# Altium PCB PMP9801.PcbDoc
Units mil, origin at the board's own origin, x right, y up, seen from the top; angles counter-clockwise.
Board outline 2509.99 x 1210.36 mil, 2 copper layers (Top Layer, Bottom Layer), stack 62 mil thick; 26 components, 15 nets, 64 pads, 17 vias.
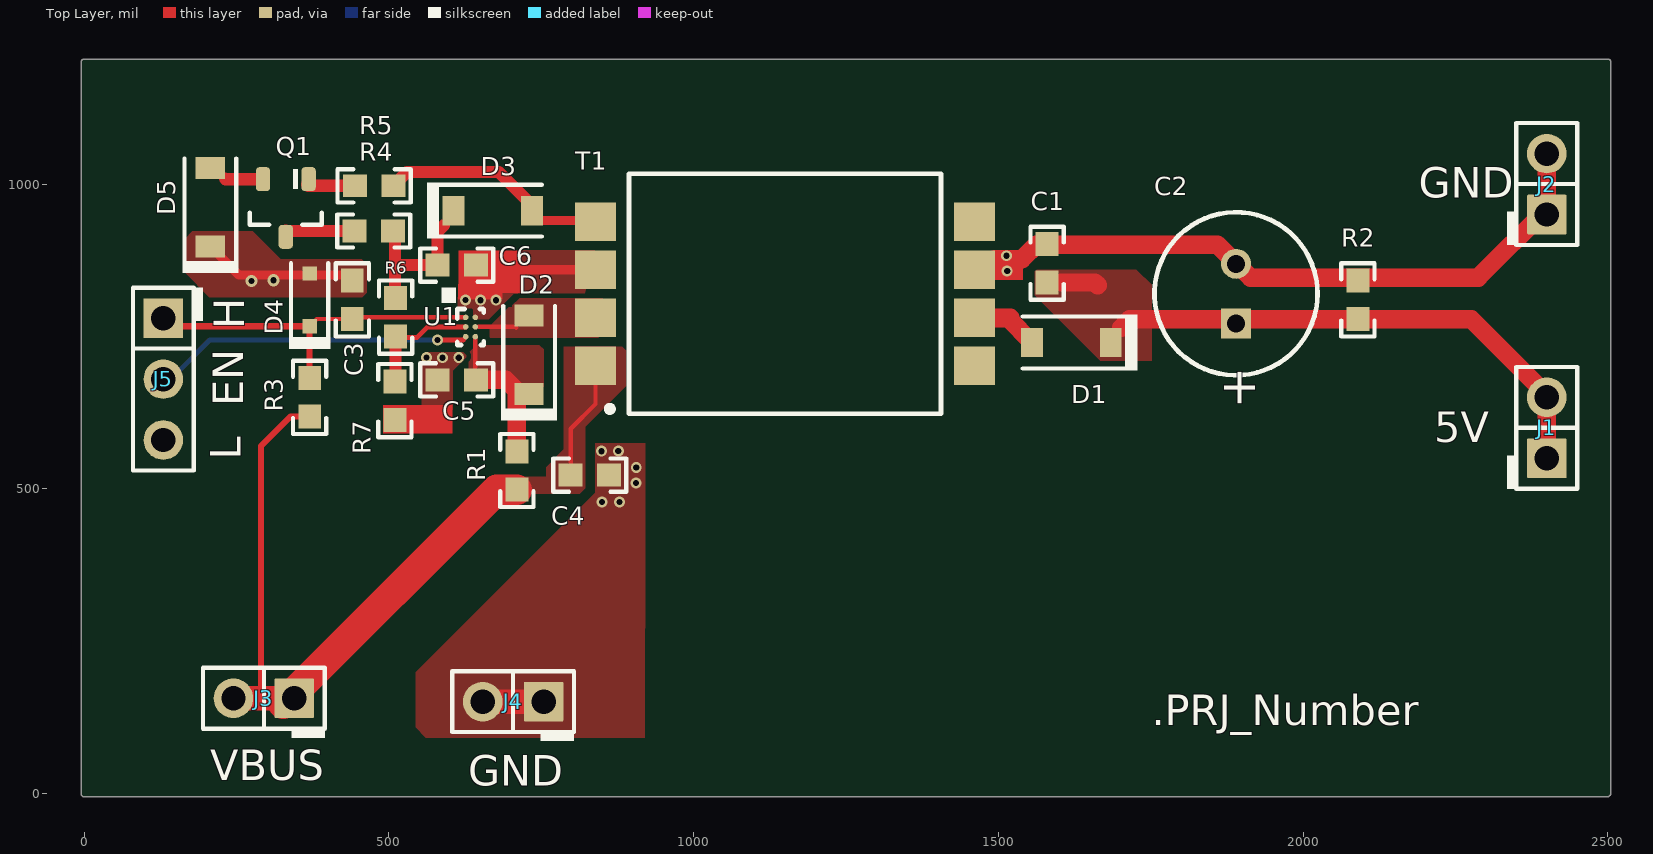
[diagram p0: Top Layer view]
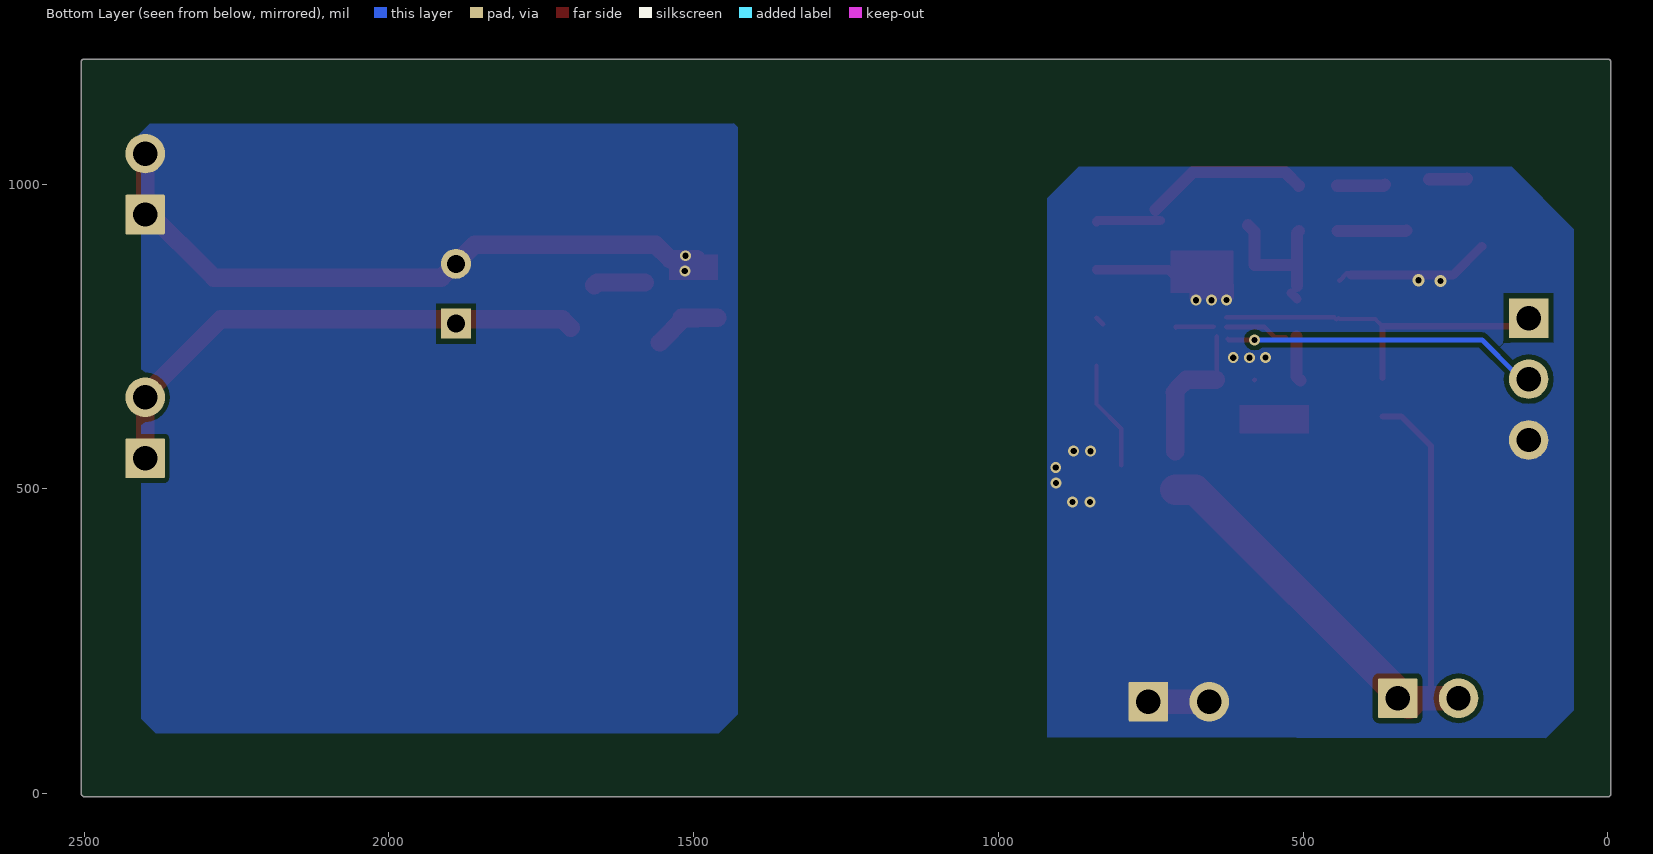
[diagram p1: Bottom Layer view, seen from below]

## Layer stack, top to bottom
Top Solder: solder mask 0.4, Solder Resist, Dk 3.5
Top Layer: signal copper 1.4
Dielectric1: core 59.2, FR-4, Dk 4.8
Bottom Layer: signal copper 1.4
Bottom Solder: solder mask 0.4, Solder Resist, Dk 3.5

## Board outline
-4.87,-0.06 cw(c0.06,0.85) -4.96,0.85 -4.96,1199.94 cw(c0.06,1199.94) 0.06,1204.96 2500.02,1204.96 cw(c2500.02,1199.94) 2505.04,1199.94 2505.04,0.48 cw(c2500.02,0.48) 2503.55,-3.08 2503.57,-3.06 2502.7,-3.93 2502.71,-3.92 cw(c2499.15,-0.39) 2499.15,-5.4 0.13,-5.4 cw(c0.13,-0.39)

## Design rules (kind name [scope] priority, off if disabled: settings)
AcuteAngle [All] p1: minimum=4.50000000000000E+0001 checktracksonly=FALSE
AssemblyTestPointUsage [All] p1: valid=2
Clearance "U1 Clearance" [InComponent('U1')] p1: gap=4
Clearance Clearance_BoardEdge [OnCopper and Not InComponentClass('Logo') and not InComponentClass('FiducialMark') and not InRegion(1000,500,4000,800) vs IsKeepOut] p2: gap=30
Clearance [All] p3: gap=8
ComponentClearance ComponentClearance_MountingHoles_FiducialMarks [InComponentClass('Mounting Holes') vs InComponentClass('FiducialMark')] p1: gap=50 collisioncheckmode=3 verticalgap=10 showdistances=FALSE
ComponentClearance ComponentClearance_SHUNT [InComponentClass('Shunt')] p2: gap=0 collisioncheckmode=3 verticalgap=0 showdistances=FALSE
ComponentClearance ComponentClearance_Logo [All] p3: gap=10 collisioncheckmode=3 verticalgap=10 showdistances=FALSE
ComponentClearance ComponentClearance_ScrewToNut [(HasFootprint('NY PMS 440 0025 PH')) vs (HasFootprint('Keystone_1902C'))] p4: gap=5 collisioncheckmode=3 verticalgap=10 showdistances=FALSE
ComponentClearance ComponentClearance_MountingHoles [InComponentClass('Mounting Holes')] p5: gap=250 collisioncheckmode=3 verticalgap=100000 showdistances=FALSE
ComponentClearance ComponentClearance_SmallPassives [HasFootprint('0201*') or HasFootprint('0402*') or HasFootprint('0508') or HasFootprint('0603*') or HasFootprint('0612') or HasFootprint('0805*') or HasFootprint('0815*') or HasFootprint('0830*') or HasFootprint('1206*') or HasFootprint('1210*') or HasFootprint('1808*') or HasFootprint('1812*') or HasFootprint('1825*') or HasFootprint('2010*') or HasFootprint('2220*') or HasFootprint('2225*') or HasFootprint('2512*') or HasFootprint('2728*') or HasFootprint('3518*') vs HasFootprint('0201*') or HasFootprint('0402*') or HasFootprint('0508') or HasFootprint('0603*') or HasFootprint('0612') or HasFootprint('0805*') or HasFootprint('0815*') or HasFootprint('0830*') or HasFootprint('1206*') or HasFootprint('1210*') or HasFootprint('1808*') or HasFootprint('1812*') or HasFootprint('1825*') or HasFootprint('2010*') or HasFootprint('2220*') or HasFootprint('2225*') or HasFootprint('2512*') or HasFootprint('2728*') or HasFootprint('3518*')] p6: gap=20 collisioncheckmode=3 verticalgap=10 showdistances=FALSE
ComponentClearance ComponentClearance_THtoSMT [IsThruComponent vs IsSMTComponent] p7 off: gap=10 collisioncheckmode=3 verticalgap=100000 showdistances=FALSE
ComponentClearance ComponentClearance_THtoTH [IsThruComponent vs IsThruComponent] p8: gap=10.11 collisioncheckmode=3 verticalgap=100000 showdistances=FALSE
ComponentClearance [All] p9: gap=10 collisioncheckmode=3 verticalgap=10 showdistances=FALSE
DiffPairsRouting [All] p1: maxlimit=100 minlimit=10 mostfreqgap=10 toplayer_minwidth=15 toplayer_maxwidth=15 toplayer_prefwidth=15 bottomlayer_minwidth=15 bottomlayer_maxwidth=15 bottomlayer_prefwidth=15 maxuncoupledlength=1000
FabricationTestPointUsage TestPointUsage [All] p1: valid=2 allowmultiple=FALSE
FabricationTestpoint Testpoint [All] p1: side=3 testpointundercomponent=TRUE minsize=40 maxsize=100 preferedsize=60 minholesize=0 maxholesize=40 preferedholesize=32 testpointgrid=1 allowsidetop=TRUE allowsidebottom=TRUE usegrid=TRUE gridtolerance=0.01
FanoutControl Fanout_LCC [IsLCC] p1: bgadir=Out bgaviamode=Centered fanoutstyle=Auto fanoutdirection=Alternating viagrid=1 // Fanout_LCC (Default Rule)
FanoutControl Fanout_BGA [IsBGA] p2: bgadir=Out bgaviamode=Centered fanoutstyle=Auto fanoutdirection=Alternating viagrid=1 // Fanout_BGA (Default Rule)
FanoutControl Fanout_Default [All] p4: bgadir=Out bgaviamode=Centered fanoutstyle=Auto fanoutdirection=Alternating viagrid=1 // Fanout_Default (Default Rule)
FanoutControl Fanout_Small [(CompPinCount < 5)] p5: bgadir=Out bgaviamode=Centered fanoutstyle=Auto fanoutdirection=OutThenIn viagrid=1 // Fanout_Small (Default Rule)
HoleSize [All] p1: absolutevalues=TRUE maxlimit=100 minlimit=8 maxpercent=80.000 minpercent=20.000
HoleToHoleClearance [All] p1: gap=1 allowstackedmicrovias=TRUE
MinimumAnnularRing MinimumAnnularRing_small [TouchesRoom('BGA_Room')] p1: minimumring=2.8
MinimumAnnularRing MinimumAnnularRing_ThermalPadVias [IsVia and InAnyComponent] p2: minimumring=5.91
MinimumAnnularRing [All] p3: minimumring=4
MinimumSolderMaskSliver MinimumSolderMaskSliver_Logo [InComponentClass('Logo') vs InComponentClass('Logo')] p1: minsoldermaskwidth=0.7
MinimumSolderMaskSliver [All] p2: minsoldermaskwidth=3
PlaneClearance [All] p1: clearance=10
PlaneConnect [All] p1: planeconnectstyle=Direct reliefexpansion=10 reliefentries=4 reliefconductorwidth=10 reliefairgap=10
PolygonConnect PolygonConnect-TH-Relief [IsPoly vs (IsThruPin)  And Not (InComponent('U3'))  And Not (InComponent('U4'))] p1: connectstyle=Direct reliefconductorwidth=20 reliefentries=4 polygonreliefangle="90 Angle" airgapwidth=10
PolygonConnect PolygonConnect-DirectConn [All] p2: connectstyle=Direct reliefconductorwidth=10 reliefentries=4 polygonreliefangle="90 Angle" airgapwidth=10
PolygonConnect [All] p3: connectstyle=Relief reliefconductorwidth=10 reliefentries=4 polygonreliefangle="90 Angle" airgapwidth=10
RoutingVias ThermalPadVias [IsVia and InAnyComponent] p1: holewidth=7.87 width=19.68 viastyle="Through Hole" minholewidth=7.87 minwidth=19.68 maxholewidth=12.99 maxwidth=23.62
RoutingVias [All] p2: holewidth=10 width=22 viastyle="Through Hole" minholewidth=4 minwidth=10 maxholewidth=100 maxwidth=100
SMDToCorner [All] p1: distance=0
SilkToBoardRegionClearance [Not ((IsComment or IsDesignator) And (Hide <> 'False')) and not InRegion(1000,500,4000,800)] p1:
SilkToSilkClearance SilkToSilkClearance_Pb-FreeLogo [(HasFootprint('Pb-Free_Overlay_Medium') OR HasFootprint('Pb-Free_Overlay_Small')) vs (HasFootprint('Pb-Free_Overlay_Medium') OR HasFootprint('Pb-Free_Overlay_Small'))] p1: silktosilkclearance=0
SilkToSilkClearance [All] p2: silktosilkclearance=3
SilkToSolderMaskClearance SilkToComonentPadClearance [IsPad and InAnycomponent] p1 off: minsilkscreentomaskgap=5 clearancetoexposedcopper=TRUE
SilkToSolderMaskClearance "Silk to Solder Mask Opening" [All] p2 off: minsilkscreentomaskgap=4 clearancetoexposedcopper=TRUE
SolderMaskExpansion [All] p1: expansion=1
Width [All] p1: maxlimit=100 minlimit=6 preferedwidth=10 checkconnectedcopper=TRUE
13 further rules are at their usual default settings.

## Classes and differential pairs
component class Header: J1 J2 J3 J4 J5

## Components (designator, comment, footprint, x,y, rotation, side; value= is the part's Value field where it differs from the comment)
C1 "GRM188R6YA225KA12D" 0603 1580,870 r90 top
C2 "EEU-EB1E101S" CAPPR250W50D630H1120 1890,820 r90 top
C3 "GRM188R61C104KA01D" 0603 440,810 r90 top
C4 "GRM188R6YA225KA12D" 0603 829.5,522.45 r0 top
C5 "GRM188R6YA225KA12D" 0603 611.31,678.7 r180 top
C6 "GRM188R6YA225KA12D" 0603 611.32,867.01 r0 top
D1 "MBR0540T1G" SOD-123 1620,740 r180 top
D2 "1N4148W-TP" SOD-123 730,720 r90 top
D3 "1N4148W-TP" SOD-123 670.61,956.33 r0 top
D4 "CMDZ5L1 TR" sod-323 370,810 r90 top
D5 "1N4148W-TP" SOD-123 206.98,962.11 r90 top
J1 "TSW-102-07-G-S" TSW-102-07-G-S 2400,600 r90 top
J2 "TSW-102-07-G-S" TSW-102-07-G-S 2400,1000 r90 top
J3 "TSW-102-07-G-S" TSW-102-07-G-S 294.97,156.23 r180 top
J4 "TSW-102-07-G-S" TSW-102-07-G-S 703.84,150.75 r180 top
J5 "TSW-103-07-G-S" TSW-103-07-G-S 130,680 r270 top
Q1 "MMBT3904" SOT-23 330.83,960.74 r270 top
R1 "RC0603FR-0710KL" 0603 710,530 r270 top
R2 "RC0603FR-072K49L" 0603 2090,810 r270 top
R3 "CRCW06035K11FKEA" 0603 370,650 r90 top
R4 "RC0603FR-07499RL" 0603 475.19,922.92 r0 top
R5 "RC0603FR-0710KL" 0603 475.71,997.17 r180 top
R6 "CRCW060349K9FKEA" 0603 510.94,781.59 r90 top
R7 "RC0603FR-0710KL" 0603 509.94,644.58 r270 top
T1 "Used in BOM report" CoilCraft_10uH 1150,820 r90 top
U1 "TPS61046YFFR" YFF0006AAAA 633.92,765.54 r0 top

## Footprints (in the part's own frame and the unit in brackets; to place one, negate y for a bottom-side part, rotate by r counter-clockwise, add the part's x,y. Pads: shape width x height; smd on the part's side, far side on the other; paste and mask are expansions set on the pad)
0603 [mm] "0603 from SM-752 data"
  rect 1x0.95 smd: 1(-0.8,0) 2(0.8,0)
  silkscreen extent -1.52,-0.69 1.52,0.69, body extent -0.87,-0.47 0.87,0.47, height 1
CAPPR250W50D630H1120 [mm] "PANASONIC"
  rect 1.25x1.25 hole 0.75: 1(-1.25,0)
  round 1.25 hole 0.75: 2(1.25,0)
  silkscreen extent -3.4,-3.4 3.4,3.4, body extent -3.37,-3.39 3.4,3.39, height 12.21
CoilCraft_10uH [mm]
  rect 1.6x1.7 smd: 1(-3,7.9) 2(-1,7.9) 3(1,7.9) 4(3,7.9) 5(3,-7.9) 6(1,-7.9) 7(-1,-7.9) 8(-3,-7.9)
  silkscreen extent -5,-6.5 5,7.42
SOD-123 [mm] "On Semi recommended land pattern"
  rect 0.915x1.22 smd: 1(-1.637,0) 2(1.637,0)
  silkscreen extent -2.74,-1.17 2.03,1.17, body extent -1.93,-0.9 1.93,0.9, height 1.35
sod-323 [mm] "NXP recommended land pattern"
  rect 0.6x0.6 smd paste-0.05: 1(-1.1,0) 2(1.1,0)
  silkscreen extent -2.06,-0.86 1.53,0.86, body extent -1.3,-0.67 1.3,0.68, height 1.1
SOT-23 [mm] "SOT23, 3-Leads, Body 2.9x1.3mm, Pitch 0.95mm, Lead Span 2.5mm, IPC Medium Density"
  rrect50% 1x0.6 smd: 1(-1.2,0.95) 2(-1.2,-0.95) 3(1.2,0)
  silkscreen extent -1.63,-1.5 0.7,1.5, body extent -1.16,-1.45 1.21,1.45, height 1
TSW-102-07-G-S [mm] "Samtec 100mil, 1x2, 230 mil above insulator"
  rrect6% 1.65x1.65 hole 1.016: 1(-1.27,0)
  round 1.65 hole 1.016: 2(1.27,0)
  silkscreen extent -2.54,-1.27 2.54,1.65, body extent -2.54,-1.27 2.54,1.27, height 8.38
TSW-103-07-G-S [mm] "Samtec 100mil, 1x3, 230 mil above insulator"
  rect 1.65x1.65 hole 1.016: 1(-2.54,0)
  round 1.65 hole 1.016: 2(0,0) 3(2.54,0)
  silkscreen extent -3.81,-1.27 3.81,1.65, body extent -3.81,-1.27 3.81,1.27, height 8.38
YFF0006AAAA [mm] "DSBGA, 6-Leads, Body 0.8x1.2mm, Pitch 0.4mm"
  round 0.23 smd paste-0.13 mask+0.038: A1(-0.2,0.4) A2(0.2,0.4) B1(-0.2,0) B2(0.2,0) C1(-0.2,-0.4) C2(0.2,-0.4)
  silkscreen extent -0.55,-0.75 0.55,0.75, body extent -0.41,-0.61 0.41,0.61, height 0.63

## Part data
C1 C4 C5 C6: "CAP, CERM, 2.2 µF, 35 V, +/- 10%, X5R, 0603"
C2: "CAP, AL, 100 µF, 25 V, +/- 20%, TH"
C3: "CAP, CERM, 0.1 µF, 16 V, +/- 10%, X5R, 0603"
D1: "Diode, Schottky, 40 V, 0.5 A, SOD-123"
D2 D3 D5: "Diode, Switching, 100 V, 0.15 A, SOD-123"
D4: "Diode, Zener, 5.1 V, 250 mW, SOD-323"
J1 J2 J3 J4: "Header, 100mil, 2x1, Gold, TH"
J5: "Header, 100mil, 3x1, Gold, TH"
Q1: library part "MMBT3904, Fairchild Semiconductor", "Transistor, NPN, 40 V, 0.2 A, SOT-23"
R1 R5 R7: "RES, 10.0 k, 1%, 0.1 W, 0603"
R2: "RES, 2.49 k, 1%, 0.1 W, 0603"
R3: "RES, 5.11 k, 1%, 0.1 W, 0603"
R4: "RES, 499, 1%, 0.1 W, 0603"
R6: "RES, 49.9 k, 1%, 0.1 W, 0603"
T1: library part CoilCraft_10uH_Transformer
U1: "28-V Output Voltage Boost Converter in WCSP Package, YFF0006AAAA"

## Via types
v1: diameter 18, hole 10, Top Layer to Bottom Layer, 15 vias
v2: diameter 20, hole 10, Top Layer to Bottom Layer, 2 vias

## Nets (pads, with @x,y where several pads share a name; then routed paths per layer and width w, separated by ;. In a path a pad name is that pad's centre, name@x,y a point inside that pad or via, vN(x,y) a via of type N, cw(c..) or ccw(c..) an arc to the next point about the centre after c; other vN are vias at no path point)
5V: C1.1 C2.1 D1.1 J1.1 J1.2 R2.2 | length 944.6
  Top Layer w30: C1.1 1658.6,838.5 1663.12,833.99 ; D1.1@1701.44,764.02 1715.38,777.95 2276.02,777.95 2400,653.98 J1.2 J1.1
EN: J5.2 U1.C1 | length 496.9
  Top Layer w8: v1@577.97,744.01 621.89,744.01 623.73,745.85
  Bottom Layer w8: J5.2@151.88,689.78 206.44,744.34 v1(579.62,744.34)
FB: R6.1 R7.1 U1.B1 | length 180.1
  Top Layer w8: R6.1@528.7,748.5 546.42,748.5 ; 546.16,748.25 546.42,748.5 ; U1.B1 563.45,765.54 546.42,748.5
  Top Layer w20: R7.1@504.46,677.49 510.94,683.98 R6.1
GND: C3.2 C4.2 C5.2 C6.2 D4.2 D5.1 J4.1 J4.2 J5.3 R7.2 T1.3 U1.A2 | length 492.3
  Top Layer w8: D4.2@370,850.48 D4.2 ; C3.2@421.3,853.31 428.19,853.31 C3.2 ; 711.5,849.37 711.5,850
  Top Layer w15: D5.1 254.14,850.48 370,850.48 C3.2@421.3,850.48 ; 711.5,850 720.87,859.37 T1.3
  Top Layer w40: J4.2 J4.1
  other v1: 849.45,478.11 878.57,478.45 905.41,509.61 905.9,534.97 848.6,561.61 876.38,561.94 561.76,715.11 588.08,714.98 614.62,715.04 650.56,809.39 675.54,809.4 625.46,810.01
  other v2: 274.35,840.8 310.67,842.11
NetD1_2: D1.2 T1.7 | length 135.9
  Top Layer w30: T1.7 1519.33,780.63 ; T1.7@1494.49,779.91 1515.62,779.91 D1.2
NetD2_2: D2.2 T1.2 U1.B2 | length 78.6
  Top Layer w8: 646.55,765.79 708.98,765.79 708.98,764.66 ; T1.2@828.35,770 T1.2
NetD3_2: D3.2 R5.1 T1.4 | length 375.1
  Top Layer w15: D3.2@734.47,940 837.09,940 T1.4
  Top Layer w20: R5.1 529.77,1019.73 680.35,1019.73 D3.2@742.13,957.96
NetD5_2: D5.2 Q1.2 | length 62.8
  Top Layer w20: D5.2@231,1008.89 231.9,1007.99 Q1.2
NetQ1_1: Q1.1 R5.2 | length 79.2
  Top Layer w20: Q1.1@365.83,999.14 367.81,997.17 R5.2
NetQ1_3: Q1.3 R4.1 | length 113.3
  Top Layer w20: Q1.3@330.72,923.67 331.46,922.92 R4.1
SGND: C1.2 C2.2 J2.1 J2.2 R2.1 T1.6 | length 1075.2
  Top Layer w30: T1.6@1494.49,876.79 1538.73,876.79 1562.36,900.41 1859.69,900.41 1913.7,846.41 2287.27,846.41 2400,959.14 J2.2
  other v1: 1514.59,857.34 1513.55,882.36
VAUX: C5.1 D2.1 R1.1 U1.C2 | length 224.7
  Top Layer w8: C5.1@641.8,690.8 U1.C2
  Top Layer w30: C5.1 691.72,678.7 D2.1@705.98,664.43 ; R1.1 710,656.97 D2.1@710.85,657.81
VBUS: C4.1 J3.1 J3.2 R1.2 R3.1 T1.1 | length 1326.8
  Top Layer w7: C4.1@798.5,538.7 798.5,598.5 838.98,638.98 T1.1
  Top Layer w10: 290,142.14 290,156.23 290,570 338.5,618.5 R3.1
  Top Layer w40: J3.2 290,156.23 J3.1@335.06,156.23
  Top Layer w50: J3.1@326.48,147.65 335.06,156.23 677.34,498.5 R1.2
VIN: C3.1 D4.1 J5.1 R3.2 U1.A1 | length 570.9
  Top Layer w7: D4.1 381.81,778.5 C3.1 C3.1@441.5,780 ; C3.1@445.52,777.78 449.02,781.29 U1.A1
  Top Layer w10: J5.1@143.31,766.69 D4.1 R3.2
VSEN: C6.1 D3.1 R4.2 R6.2 | length 240.7
  Top Layer w15: R6.2@510,811.5 R6.2@520,821.5
  Top Layer w20: R4.2 509.97,919.64 R6.2@509.97,832.77 ; 514.44,867.01 C6.1 579.82,921.77 D3.1@590.36,932.31
pads on no net: T1.5 T1.8

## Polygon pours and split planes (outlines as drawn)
VAUX on Top Layer "Top Layer-No Net 3" (solid, remove dead copper, pour order 32): 643.4,735.55 747.02,735.55 753.88,728.69 753.88,667.11 751.2,664.42 635.94,664.42 630.87,669.49 630.87,723.47 642.95,735.55
GND on Top Layer "Top Layer-No Net 2" (solid, remove dead copper, pour order 29): 838.65,574.87 920.55,574.87 920.55,271.12 919.55,270.13 919.55,91.45 560.71,91.45 543.84,108.33 543.84,198.88 709.73,364.77 838.35,493.39 838.35,573.59
GND on Top Layer "Top Layer-No Net 8" (solid, remove dead copper, pour order 35): 842.29,890.98 712.77,890.98 688.9,867.11 683.38,861.58 683.38,827.11 676.08,819.81 635.64,819.81 618.62,819.81 613.32,814.51 613.32,797.71 614.64,796.39 636.08,796.39 638.51,793.95 638.51,778.92 639.17,778.26 649.78,778.48 663.48,778.48 704.81,819.81 821.34,819.81
NetD2_2 on Top Layer "Top Layer-No Net 7" (solid, remove dead copper, pour order 34): 786.15,747.9 786.15,789.95 778.13,797.98 696.93,797.98 665.81,766.86 665.81,748.62 666.54,747.9
GND on Top Layer "Top Layer-No Net 5" (solid, remove dead copper, pour order 33): 557.93,724.38 621.68,724.38 626.97,719.09 626.97,715.8 613.27,702.1 604.87,693.7 604.87,672.69 604.87,586.48 596.83,578.44 554.28,578.44 553.91,578.8 553.91,716.89 561.03,724.02
NetD2_2 on Top Layer "Top Layer-No Net 4" (solid, remove dead copper, pour order 30): 851.2,812.68 714.32,812.68 702.67,801.03 702.67,748.61 703.32,747.96 851.85,747.96 852.82,748.93
VBUS on Top Layer "Top Layer-No Net 1" (solid, remove dead copper, pour order 27): 787.25,733.27 882.5,733.27 889.61,726.16 889.61,669.3 831.91,611.6 822.3,601.99 822.3,529.66 822.3,501.23 813.1,492.03 692.69,492.03 690.18,494.54 692.69,497.05 692.69,518.37 693.95,519.63 757.91,519.63 757.91,535.51 787.25,564.85
5V on Top Layer "Top Layer-No Net" (solid, remove dead copper, pour order 26): 1751.41,711.2 1751.41,834.45 1726.58,859.29 1562.86,859.29 1560.1,856.53 1560.1,817.44 1568.84,808.7 1667.25,710.28 1751.41,710.28
GND on Top Layer "GND_L01_P037" (solid, remove dead copper, pour order 37): 463.54,821.26 463.54,868.38 455.19,876.73 322.66,876.73 277,922.38 177.35,922.38 165.57,910.6 165.57,854.15 205.33,814.39 456.67,814.39 463.54,821.26
SGND on Bottom Layer "Bottom Layer-No Net" (solid, remove dead copper, pour order 28): 1427.25,1099.89 1427.25,130.09 1458.81,98.53 2382.2,98.53 2406.07,122.39 2406.07,1069.5 2414.17,1077.61 2392.67,1099.11 2165.91,1099.11
GND on Bottom Layer "Bottom Layer-No Net 1" (solid, remove dead copper, pour order 31): 919.95,92.31 919.95,976.65 868.36,1028.24 157.74,1028.24 55.65,926.15 55.65,136.46 101.69,90.42

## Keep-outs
Keep-Out Layer:
  text ".Layer_Name" at 577,-858.49 h60

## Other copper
Top Layer:
  rectangle net GND: 613.16,810.75 686.41,835.83
  rectangle net GND: 614.11,821.07 717.26,890.8
  rectangle net GND: 490.3,590.88 604.41,637.55
  rectangle net SGND: 1460.22,842.56 1540.59,884.24
  text ".Layer_Name" at 577,-858.49 h60
Bottom Layer:
  text ".Layer_Name" at 577,-858.49 h60

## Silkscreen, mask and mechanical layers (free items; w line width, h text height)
Top Overlay:
  rectangle: 586.59,804.49 610.03,830.45
  text "GND" at 2189.76,977.51 h50
  text "H" at 262.39,761.89 h50 r90
  text "EN" at 261.36,635.25 h50 r90
  text "5V" at 2215.3,576.25 h50
  text "L" at 257.24,547.74 h50 r90
  text ".PRJ_Number" at 1751.87,112.38 h50
  text "VBUS" at 207.18,21.79 h50
  text "GND" at 630.27,12.55 h50
  text ".Layer_Name" at 577,-858.49 h60
Bottom Overlay:
  text ".Layer_Name" at 577,-858.49 h60
Top Paste:
  text ".Layer_Name" at 577,-858.49 h60
Bottom Paste:
  text ".Layer_Name" at 577,-858.49 h60
Top Solder:
  text ".Layer_Name" at 577,-858.49 h60
  text ".Layer_Name" at 577,-858.49 h60
Bottom Solder:
  text ".Layer_Name" at 577,-858.49 h60
Drill Guide:
  text ".Layer_Name" at 577,-858.49 h60
M1 Board Outline:
  lines w10: 0.06,0.85 0.06,1199.94 2500.02,1199.94 2500.02,0.48 2499.15,-0.39 0.13,-0.39
  text ".Layer_Name" at 577,-858.49 h60
M2 Board Dimensions:
  rectangle: 125,-400 500,-275
  rectangle: 0,-275 125,-150
  lines w7: 0,-275 1000,-275 ; 125,-400 125,-150 ; 250,-400 250,-150 ; 500,-400 500,-150 ; 750,-400 750,-150 ; 0,-400 0,-150 1000,-150 1000,-400 0,-400
  text ".Layer_Name" at 577,-858.49 h60
M3 3D STEP Top:
  text ".Layer_Name" at 577,-858.49 h60
M4 3D STEP Bottom:
  text ".Layer_Name" at 577,-858.49 h60
M5 Assembly Top:
  lines w10: -292,-930.17 6308,-930.17 ; -292,-726.83 6310,-726.83 ; -292,-523.5 -292,-1133.5 3713,-1133.5 6310,-1133.5 6310,-523.5 -291.5,-523.5 -291.5,-1133.5 1284,-1133.5 ; 2173,-1133.5 2173,-523.5 ; 3440,-726.83 3440,-523.5 ; 4280,-726.83 4280,-523.5 ; 4902,-1140 4902,-937.17
  text "COMPONENTS MARKED 'DNP' SHOULD NOT BE POPULATED." at 1153.5,-318.5 h60
  text "ASSEMBLY VARIANT:" at 1153,-434 h60
  text ".VariantName" at 2189,-434 h60
  text "PCB VIEWED FROM TOP SIDE" at -228.5,-655.67 h60
  text "BOARD #:" at 2248,-655.67 h60
  text ".PRJ_Number" at 2793.5,-655.67 h60
  text "REV:" at 3638,-655.67 h60
  text ".PCB_Rev" at 3929.5,-655.67 h60
  text "SVN REV:" at 4476,-655.67 h60
  text ".VersionControl_RevNumber" at 4982,-655.67 h60
  text "TID #:" at 2248,-859 h60
  text ".TID" at 2793.5,-859 h60
  text "PLOT NAME =" at -228.5,-1064.34 h60
  text ".plot_File_Name" at 577,-1064.34 h60
  text "GENERATED    :" at 2250,-1064.34 h60
  text ".Print_Date" at 3119.5,-1064.34 h60
  text ".Print_Time" at 3848.5,-1064.34 h60
  text "TEXAS INSTRUMENTS" at 5113,-1064.34 h60
M6 Assembly Bottom:
  lines w10: -292.5,-727.33 6309.5,-727.33 ; -290.5,-930.67 6309.5,-930.67 ; 1115.5,-1140.5 1115.5,-937.67 ; 1737.5,-727.33 1737.5,-524 ; 2577.5,-727.33 2577.5,-524 ; 3844.5,-1134 3844.5,-524 ; 4733.5,-1134 6309,-1134 6309,-524 -292.5,-524 -292.5,-1134 2304.5,-1134 6309.5,-1134 6309.5,-524
  text "COMPONENTS MARKED 'DNP' SHOULD NOT BE POPULATED." at 6102,-318 h60
  text ".VariantName" at 5058,-434 h60
  text "ASSEMBLY VARIANT:" at 6097,-434 h60
  text ".VersionControl_RevNumber" at 1035.5,-656.17 h60
  text "SVN REV:" at 1541.5,-656.17 h60
  text ".PCB_Rev" at 2088,-656.17 h60
  text "REV:" at 2379.5,-656.17 h60
  text ".PRJ_Number" at 3224,-656.17 h60
  text "BOARD #:" at 3769.5,-656.17 h60
  text "PCB VIEWED FROM BOTTOM SIDE" at 6246,-656.17 h60
  text ".TID" at 3224,-859.5 h60
  text "TID #:" at 3769.5,-859.5 h60
  text "TEXAS INSTRUMENTS" at 904.5,-1064.84 h60
  text ".Print_Time" at 2169,-1064.84 h60
  text ".Print_Date" at 2898,-1064.84 h60
  text "GENERATED    :" at 3767.5,-1064.84 h60
  text ".plot_File_Name" at 5440.5,-1064.84 h60
  text "PLOT NAME =" at 6246,-1064.84 h60
M9 Title Sheet:
  drawing of 57 lines, arcs and shapes, not listed
  text "1" at 739.84,8036.5 h70
  text "2" at 3235.5,8036.5 h70
  text "3" at 5724.84,8036.5 h70
  text "4" at 8231.51,8036.5 h70
  text "5" at 10730.5,8036.5 h70
  text "6" at 13235.5,8036.5 h70
  text "A" at -416.5,6893.5 h70
  text "A" at 14383.5,6893.5 h70
  text "B" at -416.5,4513.5 h70
  text "B" at 14383.5,4513.5 h70
  text "C" at -416.5,2138.5 h70
  text "C" at 14383.5,2138.5 h70
  text "PROJECT TITLE:" at 11343.5,277.5 h45
  text ".PRJ_Title" at 11393.5,144.17 h70
  text "DESIGNED FOR:" at 11343.5,-23.5 h45
  text ".PRJ_Customer" at 11393.5,-163.5 h70
  text "D" at -416.5,-231.5 h70
  text "D" at 14383.5,-231.5 h70
  text "FILE NAME:" at 11343.5,-323.5 h45
  text ".PCB_File_Name_No_Path" at 11393.5,-443.5 h70
  text "Texas Instruments (TI) and/or its licensors do not warrant the accuracy or completeness of this specification" at 6374,-605.34 h45
  text "ENGINEER:" at 11343.5,-613.5 h45
  text "LAYOUT BY:" at 12848.5,-613.5 h45
  text "or any information contained therein. TI and/or its licensors do not warrant that this design will meet" at 6329.01,-718 h45
  text ".PRJ_Engineer" at 11393.5,-768.49 h70
  text ".PCB_Layout" at 12899,-768.49 h70
  text "the specifications, will be suitable for your application or fit for any particular purpose, or will operate in" at 6329.01,-830.67 h45
  text ".Layer_Name" at 577,-858.49 h60
  text "ALTIUM DESIGNER VERSION:" at 12848.5,-923.5 h45
  text "an implementation. TI and/or its licensors do not warrant that the design is production worthy. You should" at 6329.01,-943.33 h45
  text "completely validate and test your design implementation to confirm the system functionality for your application." at 6374,-1056 h45
  text ".print_Scale" at 11393.5,-1056.83 h70
  text ".Application_BuildNumber" at 12899,-1056.83 h70
  text "1" at 739.84,-1263.5 h70
  text "2" at 3235.5,-1263.5 h70
  text "3" at 5724.84,-1263.5 h70
  text "4" at 8231.51,-1263.5 h70
  text "5" at 10730.5,-1263.5 h70
  text "6" at 13235.5,-1263.5 h70
M10 Fab Notes:
  drawing of 173 lines, arcs and shapes, not listed
  text "DESIGN INFORMATION" at 12377.02,6201 h60
  text "MIN. TRACK WIDTH:" at 11732.46,6021 h60
  text "8" at 12828.7,6021 h60
  text "MIL" at 12983.46,6021 h60
  text "MIN. CLEARANCE:" at 11732.46,5889 h60
  text "0.2" at 12768.7,5889 h60
  text "mm" at 12983.46,5889 h60
  text "MIN. VIA PAD SIZE:" at 11732.46,5757 h60
  text "24" at 12798.71,5757 h60
  text "MIL" at 12983.46,5757 h60
  text "0.05mm (2MIL)" at 12427.46,5615.29 h60
  text "MINIMUM ANNULAR RING" at 11403.23,5611 h60
  text "EXTERNAL" at 13135.46,5611 h60
  text "PER" at 11603.23,5493 h60
  text "IPC-D-275 CLASS 2 LEVEL C" at 11823.23,5493 h60
  text "MIL, HOLES" at 13311.46,5380.71 h60
  text "+/-" at 12919,5380 h60
  text "+/-" at 13773,5380 h60
  text "REGISTRATION TOLERANCES:" at 11403.23,5375 h60
  text "METAL" at 12603,5375 h60
  text "5" at 13179.2,5375 h60
  text "3" at 14012.2,5375 h60
  text "MIL" at 14128.46,5375 h60
  text "+/-" at 13773,5262 h60
  text "HOLE SIZE TOLERANCE (UNLESS OTHERWISE SPECIFIED):" at 11403.23,5257 h60
  text "3" at 14012.2,5257 h60
  text "MIL" at 14128.46,5257 h60
  text "MATERIAL:" at 11328.46,5047.54 h60
  text "FR-4 High Tg" at 12314.9,4907.21 h60
  text "FR-408" at 11749.46,4898.64 h60
  text "OTHER" at 13237.46,4898.64 h60
  text "X" at 12160,4895 h60
  text "62 MIL (1.6mm) +/-10%" at 12069.56,4735.92 h60
  text "THICKNESS:" at 11403.23,4731.64 h60
  text "X" at 11941.4,4731.64 h60
  text "OTHER" at 13354.46,4731.64 h60
  text "TOLERANCE:" at 11403.23,4573.64 h60
  text "X" at 12242.53,4573.64 h60
  text "ANSI IPC-6012 TYPE 3 CLASS 2" at 12429.48,4573.64 h60
  text "OTHER +/-" at 12429.46,4417.64 h60
  text "BOW & TWIST:" at 11403.23,4260.64 h60
  text "X" at 12242.53,4260.64 h60
  text "ANSI IPC-6012 TYPE 3 CLASS 2" at 12429.48,4260.64 h60
  text "OTHER +/-" at 12429.46,4102.13 h60
  text "DRILLING:" at 11328.46,3963.64 h60
  text "REFERENCE:" at 11403.23,3846.64 h60
  text "X" at 12051.46,3846.64 h60
  text "AS SHOWN" at 12238.46,3846.64 h60
  text "X" at 12952.46,3846.64 h60
  text "NC_DRILL FILES" at 13089.46,3846.64 h60
  text "PTH COPPER THICKNESS:" at 11403.23,3688.64 h60
  text "X" at 12533.46,3688.64 h60
  text "20-30 um" at 12670.46,3688.64 h60
  text "OTHER" at 13387.46,3688.64 h60
  text "BOARD FINISH:" at 11328.46,3529.64 h60
  text "SILKSCREEN:" at 11483.68,3411.64 h60
  text "X" at 12432.46,3411.64 h60
  text "TOP" at 12558.46,3411.64 h60
  text "X" at 12942.46,3411.64 h60
  text "BOTTOM" at 13069.46,3411.64 h60
  text "SILKSCREEN COLOR:" at 11483.68,3244.64 h60
  text "X" at 12431.42,3244.64 h60
  text "WHITE" at 12558.46,3244.64 h60
  text "OTHER" at 13069.46,3244.64 h60
  text "X" at 12562.42,3085.44 h60
  text "GREEN" at 12689.46,3085.44 h60
  text "OTHER" at 13307.46,3085.44 h60
  text "SOLDER RESIST COLOR:" at 11483.68,3074.64 h60
  text "X" at 12562.42,2915.44 h60
  text "MATTE" at 12689.46,2915.44 h60
  text "SEMI-GLOSS" at 13307,2914.8 h60
  text "IMMERSION GOLD (ENIG)" at 12389.46,2726.92 h60
  text "ENEPIG" at 13727,2723.64 h60
  text "SURFACE FINISH:" at 11328.46,2722.64 h60
  text "X" at 12202.51,2722.64 h60
  text "IMM. TIN/SILVER OR EQUIV" at 11658,2565.64 h60
  text "OTHER" at 13089.46,2565.64 h60
  text "ARRAY/PANEL:" at 11328.46,2386.64 h60
  text "CUT AND TRIM PER M1 BOARD OUTLINE" at 12389.46,2382.35 h60
  text "N.C. ROUTE" at 12389.46,2230.64 h60
  text "X" at 13068.46,2230.64 h60
  text "V. SCORE" at 13255.46,2230.64 h60
  text "CERTIFICATION:" at 11328.46,2093.64 h60
  text "MATERIALS AND WORKMANSHIP FOR ALL PCBS" at 12053.46,2093.64 h60
  text "TO MEET OR EXCEED THE REQUIREMENTS OF:" at 12053.46,1995.64 h60
  text "X" at 11679.96,1859.13 h60
  text "ANSI IPC-A-600F CLASS ->" at 11818.96,1859.13 h60
  text "X" at 13458.02,1859.13 h60
  text "2" at 13576.96,1859.14 h60
  text "1" at 13261.96,1857.64 h60
  text "3" at 13930.96,1857.64 h60
  text "X" at 12494.02,1699.64 h60
  text "RoHS" at 12630.96,1699.64 h60
  text "OTHER" at 13275.36,1699.64 h60
  text "PER ORDER" at 13672.42,1699.64 h60
  text "ALL BOARDS MUST MEET OR EXCEED UL94-V0 REQUIREMENTS." at 11356,1534 h60
  text "PCB MUST BEAR THE UL94V-0 UL REGISTERED MATERIAL ID NUMBER" at 11356,1414 h60
  text "ADDITIONAL REQUIREMENTS:" at 11328.46,1240.64 h60
  text "MICROSECTION:" at 11403.23,1125.64 h60
  text "YES" at 12308.96,1125.64 h60
  text "REQUIRED" at 13170.46,969.49 h60
  text "BARE BOARD ELEC. TEST:" at 11403.23,966.64 h60
  text "NONE" at 12708.96,966.64 h60
  text "X" at 13043.46,966.64 h60
  text "PER ORDER" at 13762.46,966.64 h60
  text ".Layer_Name" at 577,-858.49 h60
M11 Gerber Information:
  lines w10: -292,-930.17 6308,-930.17 ; -292,-726.83 6310,-726.83 ; -292,-523.5 -292,-1133.5 3713,-1133.5 6310,-1133.5 6310,-523.5 -291.5,-523.5 -291.5,-1133.5 1284,-1133.5 ; 2173,-1133.5 2173,-523.5 ; 3440,-726.83 3440,-523.5 ; 4280,-726.83 4280,-523.5 ; 4902,-1140 4902,-937.17
  text "ALL ARTWORK VIEWED FROM TOP SIDE" at -228.5,-655.67 h60
  text "BOARD #:" at 2248,-655.67 h60
  text ".PRJ_Number" at 2793.5,-655.67 h60
  text "REV:" at 3638,-655.67 h60
  text ".PCB_Rev" at 3929.5,-655.67 h60
  text "SVN REV:" at 4476,-655.67 h60
  text ".VersionControl_RevNumber" at 4982,-655.67 h60
  text "LAYER NAME =" at -228.5,-858.49 h60
  text "TID #:" at 2248,-859 h60
  text ".TID" at 2793.5,-859 h60
  text "PLOT NAME =" at -228.5,-1064.34 h60
  text ".plot_File_Name" at 577,-1064.34 h60
  text "GENERATED    :" at 2250,-1064.34 h60
  text ".Print_Date" at 3119.5,-1064.34 h60
  text ".Print_Time" at 3848.5,-1064.34 h60
  text "TEXAS INSTRUMENTS" at 5113,-1064.34 h60
M12 Stackup:
  drawing of 191 lines, arcs and shapes, not listed
  text "Layer" at 9790.34,7830 h60
  text "Name" at 10200.26,7830 h60
  text "Material" at 11130,7830 h60
  text "Thickness" at 11989.77,7830 h60
  text "Constant" at 12639.6,7830 h60
  text "Board Layer Stack" at 13209.46,7830 h60
  text "1" at 9790.34,7710 h60
  text "Top Overlay" at 10200.26,7710 h60
  text "2" at 9790.34,7590 h60
  text "Top Solder" at 10200.26,7590 h60
  text "Solder Resist" at 11130,7590 h60
  text "0.40mil" at 11989.77,7590 h60
  text "3.5" at 12639.6,7590 h60
  text "3" at 9790.34,7470 h60
  text "Top Layer" at 10200.26,7470 h60
  text "Copper" at 11130,7470 h60
  text "1.40mil" at 11989.77,7470 h60
  text "4" at 9790.34,7350 h60
  text "Dielectric1" at 10200.26,7350 h60
  text "FR-4" at 11130,7350 h60
  text "59.20mil" at 11989.77,7350 h60
  text "4.8" at 12639.6,7350 h60
  text "5" at 9790.34,7230 h60
  text "Bottom Layer" at 10200.26,7230 h60
  text "Copper" at 11130,7230 h60
  text "1.40mil" at 11989.77,7230 h60
  text "6" at 9790.34,7110 h60
  text "Bottom Solder" at 10200.26,7110 h60
  text "Solder Resist" at 11130,7110 h60
  text "0.40mil" at 11989.77,7110 h60
  text "3.5" at 12639.6,7110 h60
  text "7" at 9790.34,6990 h60
  text "Bottom Overlay" at 10200.26,6990 h60
  text ".Layer_Name" at 577,-858.49 h60
M13 Component Bodies Top:
  text ".Layer_Name" at 577,-858.49 h60
M14 Component Bodies Bottom:
  text ".Layer_Name" at 577,-858.49 h60
M15 Courtyards Top:
  text ".Layer_Name" at 577,-858.49 h60
M16 Courtyards Bottom:
  text ".Layer_Name" at 577,-858.49 h60
Drill Drawing:
  lines w10: 5656.09,2990.02 5683.72,3003.83 5711.34,2990.02 5697.53,3017.64 5711.34,3045.27 5683.72,3031.46 5656.09,3045.27 5669.9,3017.64 5656.09,2990.02 ; 5656.09,3128.15 5669.9,3128.15 5669.9,3114.34 5697.53,3114.34 5697.53,3128.15 5711.34,3128.15 5711.34,3155.78 5697.53,3155.78 5697.53,3169.59 5669.9,3169.59 5669.9,3155.78 5656.09,3155.78 5656.09,3128.15 ; 5656.09,3238.66 5656.09,3252.47 5669.9,3266.28 5656.09,3280.1 5656.09,3293.91 5669.9,3293.91 5683.72,3280.1 5697.53,3293.91 5711.34,3293.91 5711.34,3280.1 5697.53,3266.28 5711.34,3252.47 5711.34,3238.66 5697.53,3238.66 5683.72,3252.47 5669.9,3238.66 5656.09,3238.66
  lines w12: 5606,2952.72 7584.02,2952.72 ; 5606,3325.68 7584.02,3325.68 ; 5943.86,2828.4 5943.86,3450 ; 6275.86,2828.4 6275.86,3450 ; 6912.43,2828.4 6912.43,3450 ; 7171.57,2828.4 7171.57,3450 ; 5606,2828.4 7584.02,2828.4 7584.02,3450 5606,3450 5606,2828.4
  text "Symbol" at 5680.59,3362.98 h72
  text "Quantity" at 5981.16,3362.98 h72
  text "Finished Hole Size" at 6313.16,3362.98 h72
  text "Plated" at 6949.72,3362.98 h72
  text "Hole Type" at 7208.86,3362.98 h72
  text "17" at 5981.16,3238.66 h60
  text "10.00mil (0.254mm)" at 6313.16,3238.66 h60
  text "PTH" at 6949.72,3238.66 h60
  text "Round" at 7208.86,3238.66 h60
  text "2" at 5981.16,3114.34 h60
  text "29.53mil (0.750mm)" at 6313.16,3114.34 h60
  text "PTH" at 6949.72,3114.34 h60
  text "Round" at 7208.86,3114.34 h60
  text "11" at 5981.16,2990.02 h60
  text "40.00mil (1.016mm)" at 6313.16,2990.02 h60
  text "PTH" at 6949.72,2990.02 h60
  text "Round" at 7208.86,2990.02 h60
  text "30 Total" at 5981.16,2865.7 h60
  text ".Layer_Name" at 577,-858.49 h60

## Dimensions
0,0 to 2500.02,0.48 on M2 Board Dimensions
0,0 to 0.06,1199.94 on M2 Board Dimensions
0,-400 to 1000,-400 on M2 Board Dimensions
